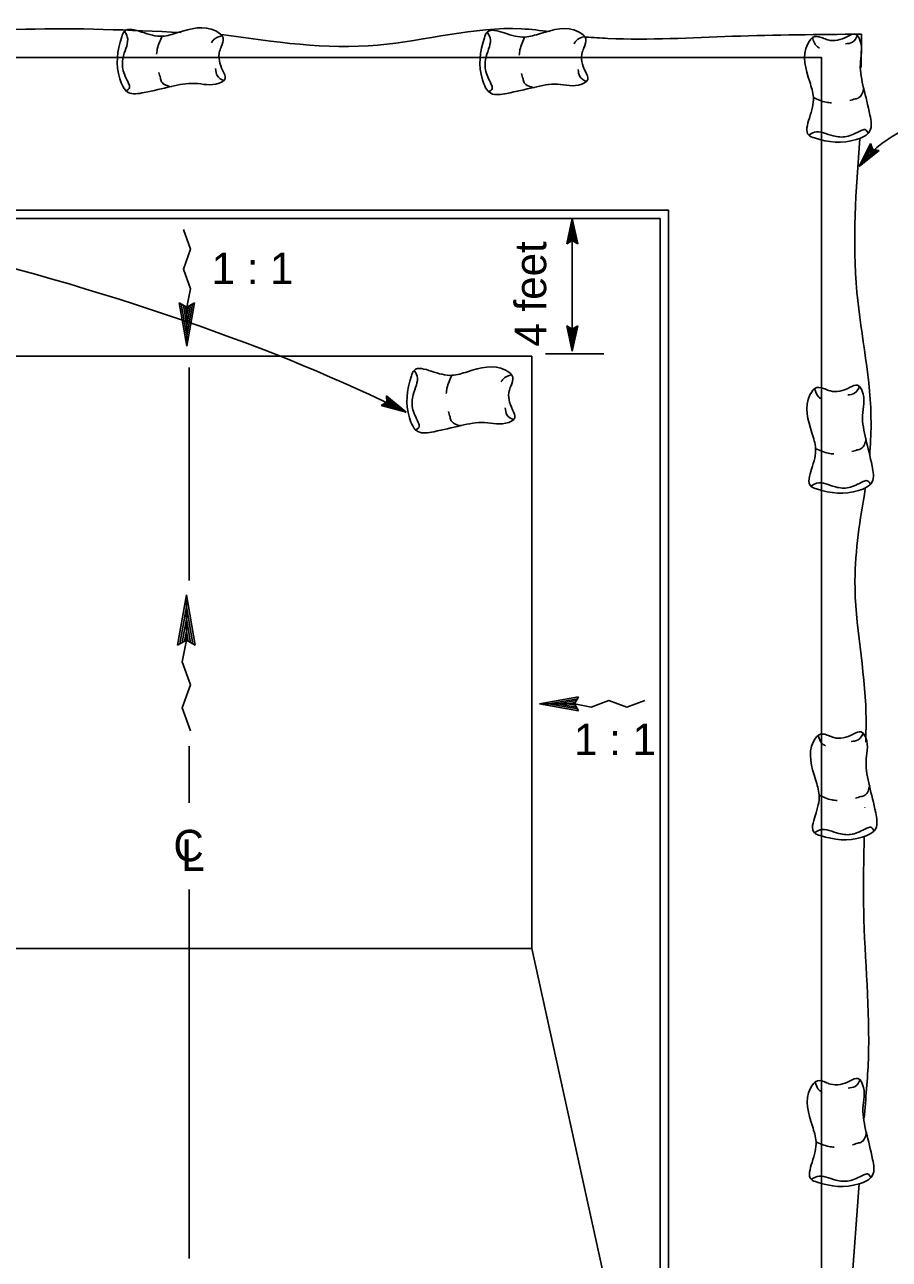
# Model space of a CAD drawing. Extents: x 6707406 to 6714471, y 1868570 to 1872341.
# Drawn here: x 6709027.7 to 6709225.4, y 1868819.1 to 1869101.6 of the extents above; entities that cross this region are included whole.
import ezdxf

# ---------------------------------------------------------------- set-up
doc = ezdxf.new("R2010")
doc.units = 0
for name, color, linetype in [('56 Stg 3 Anno', 7, 'Continuous'), ('57 Undefined', 7, 'Continuous'), ('60 Nongeo Data', 7, 'Continuous')]:
    doc.layers.add(name, color=color, linetype=linetype)

msp = doc.modelspace()

# ---------------------------------------------------------------- linework, layer by layer
at = {"layer": '56 Stg 3 Anno'}
for p, q in [((6709218.56, 1869069.08), (6709221.13, 1869074.39)), ((6709219.39, 1869070.13), (6709221.26, 1869074)), ((6709220.21, 1869071.16), (6709221.42, 1869073.66)), ((6709221.03, 1869072.2), (6709221.55, 1869073.27)), ((6709221.13, 1869074.39), (6709221.13, 1869074.39)), ((6709221.13, 1869074.39), (6709221.66, 1869073)), ((6709223.14, 1869072.8), (6709218.56, 1869069.08)), ((6709222.74, 1869072.85), (6709219.38, 1869070.12)), ((6709222.33, 1869072.89), (6709220.21, 1869071.16)), ((6709221.97, 1869072.96), (6709221.03, 1869072.2)), ((6709221.66, 1869073), (6709223.14, 1869072.8)), ((6709223.14, 1869072.8), (6709223.14, 1869072.8)), ((6709218.56, 1869069.08), (6709218.56, 1869069.08)), ((6709151.64, 1869051.43), (6709152.93, 1869057.19)), ((6709151.64, 1869051.43), (6709152.93, 1869057.19)), ((6709152.93, 1869026.86), (6709152.93, 1869057.19)), ((6709152.93, 1869057.19), (6709152.93, 1869057.19)), ((6709152.93, 1869057.19), (6709154.21, 1869051.43)), ((6709152.93, 1869057.19), (6709152.93, 1869057.19)), ((6709152.93, 1869057.19), (6709154.21, 1869051.43)), ((6709151.98, 1869051.64), (6709152.93, 1869055.87)), ((6709151.98, 1869051.64), (6709152.93, 1869055.87)), ((6709152.33, 1869051.87), (6709152.93, 1869054.54)), ((6709152.33, 1869051.87), (6709152.93, 1869054.54)), ((6709152.93, 1869055.86), (6709153.86, 1869051.66)), ((6709152.93, 1869055.86), (6709153.86, 1869051.66)), ((6709152.93, 1869054.54), (6709153.53, 1869051.83)), ((6709152.93, 1869054.54), (6709153.53, 1869051.83)), ((6709152.93, 1869052.2), (6709151.64, 1869051.43)), ((6709152.93, 1869052.2), (6709151.64, 1869051.43)), ((6709151.64, 1869051.43), (6709151.64, 1869051.43)), ((6709151.64, 1869051.43), (6709151.64, 1869051.43)), ((6709152.66, 1869052.04), (6709152.93, 1869053.22)), ((6709152.66, 1869052.04), (6709152.93, 1869053.22)), ((6709152.93, 1869053.22), (6709153.18, 1869052.05)), ((6709152.93, 1869053.22), (6709153.18, 1869052.05)), ((6709154.21, 1869051.43), (6709152.93, 1869052.2)), ((6709154.21, 1869051.43), (6709152.93, 1869052.2)), ((6709154.21, 1869051.43), (6709154.21, 1869051.43)), ((6709154.21, 1869051.43), (6709154.21, 1869051.43)), ((6709064.77, 1869028.01), (6709063.02, 1869037.91)), ((6709063.02, 1869037.91), (6709064.77, 1869036.89)), ((6709064.77, 1869030.38), (6709063.48, 1869037.64)), ((6709064.77, 1869032.73), (6709063.95, 1869037.36)), ((6709064.77, 1869035.13), (6709064.42, 1869037.09)), ((6709066.51, 1869037.91), (6709064.77, 1869028.01)), ((6709064.77, 1869036.89), (6709066.51, 1869037.91)), ((6709066.05, 1869037.64), (6709064.77, 1869030.38)), ((6709065.58, 1869037.36), (6709064.77, 1869032.73)), ((6709065.11, 1869037.09), (6709064.77, 1869035.13)), ((6709152.93, 1869026.86), (6709151.65, 1869032.62)), ((6709151.65, 1869032.62), (6709151.65, 1869032.62)), ((6709151.65, 1869032.62), (6709152.93, 1869031.86)), ((6709152.93, 1869028.2), (6709152, 1869032.4)), ((6709152.93, 1869029.52), (6709152.33, 1869032.23)), ((6709152.93, 1869030.84), (6709152.67, 1869032)), ((6709152.93, 1869031.86), (6709154.22, 1869032.62)), ((6709154.22, 1869032.62), (6709152.93, 1869026.86)), ((6709153.87, 1869032.42), (6709152.93, 1869028.19)), ((6709153.53, 1869032.19), (6709152.93, 1869029.52)), ((6709153.2, 1869032.02), (6709152.93, 1869030.84)), ((6709154.22, 1869032.62), (6709154.22, 1869032.62)), ((6709146.76, 1869026.26), (6709160.13, 1869026.26)), ((6709152.93, 1869026.86), (6709152.93, 1869026.86)), ((6709065.3, 1868974.39), (6709065.3, 1869023.08)), ((6709109.21, 1869014.39), (6709110.49, 1869015.17)), ((6709114.91, 1869012.86), (6709109.21, 1869014.39)), ((6709109.21, 1869014.39), (6709109.21, 1869014.39)), ((6709113.73, 1869013.47), (6709109.57, 1869014.59)), ((6709112.56, 1869014.09), (6709109.88, 1869014.81)), ((6709111.39, 1869014.7), (6709110.24, 1869015.01)), ((6709110.49, 1869015.17), (6709110.4, 1869016.66)), ((6709110.4, 1869016.66), (6709110.4, 1869016.66)), ((6709110.4, 1869016.66), (6709114.91, 1869012.86)), ((6709110.43, 1869016.26), (6709113.74, 1869013.47)), ((6709110.46, 1869015.48), (6709111.39, 1869014.7)), ((6709110.47, 1869015.85), (6709112.56, 1869014.09)), ((6709114.91, 1869012.86), (6709114.91, 1869012.86)), ((6709062.6, 1868959.55), (6709064.64, 1868971.09)), ((6709064.64, 1868971.09), (6709066.68, 1868959.55)), ((6709063.14, 1868959.86), (6709064.64, 1868968.33)), ((6709064.64, 1868968.33), (6709066.14, 1868959.86)), ((6709063.69, 1868960.18), (6709064.64, 1868965.59)), ((6709064.64, 1868965.59), (6709065.59, 1868960.18)), ((6709064.64, 1868960.73), (6709062.6, 1868959.55)), ((6709064.24, 1868960.5), (6709064.64, 1868962.78)), ((6709064.64, 1868962.78), (6709065.04, 1868960.5)), ((6709066.68, 1868959.55), (6709064.64, 1868960.73)), ((6709145.4, 1868946.17), (6709154.33, 1868947.75)), ((6709154.33, 1868944.6), (6709145.4, 1868946.17)), ((6709147.53, 1868946.17), (6709154.08, 1868947.33)), ((6709154.08, 1868945.01), (6709147.53, 1868946.17)), ((6709149.65, 1868946.17), (6709153.84, 1868946.91)), ((6709153.84, 1868945.44), (6709149.65, 1868946.17)), ((6709151.82, 1868946.17), (6709153.59, 1868946.49)), ((6709153.59, 1868945.86), (6709151.82, 1868946.17)), ((6709154.33, 1868947.75), (6709153.42, 1868946.17)), ((6709153.42, 1868946.17), (6709154.33, 1868944.6)), ((6709065.3, 1868923.55), (6709065.3, 1868936.5)), ((6709065.3, 1868819.27), (6709065.3, 1868903.71))]:
    msp.add_line(p, q, dxfattribs=at)
for points in [[(6709063.95, 1869054.7), (6709065.58, 1869050.17), (6709063.95, 1869045.64), (6709065.58, 1869041.11), (6709064.77, 1869036.89), (6709064.77, 1869028.01)], [(6709065.59, 1868939.96), (6709063.69, 1868945.24), (6709065.59, 1868950.53), (6709063.69, 1868955.81), (6709064.64, 1868960.73), (6709064.64, 1868971.09)], [(6709169.49, 1868946.91), (6709165.4, 1868945.44), (6709161.31, 1868946.91), (6709157.22, 1868945.44), (6709153.42, 1868946.17), (6709145.4, 1868946.17)]]:
    msp.add_lwpolyline(points, dxfattribs=at)
for centre, major_axis, ratio, start_param, end_param in [((6709230.16, 1869064.46), (-14.41, -12.25), 0.619917, 3.775635, 5.024737), ((6708995.51, 1869014.62), (158.62, -38.37), 0.230593, 0.776019, 2.395591)]:
    msp.add_ellipse(centre, major_axis=major_axis, ratio=ratio, start_param=start_param, end_param=end_param, dxfattribs=at)
at = {"layer": '60 Nongeo Data'}
for p, q in [((6709219.12, 1869099.36), (6709218.98, 1869091.78)), ((6709219.85, 1868922.53), (6709219.85, 1868922.43)), ((6708987.05, 1868890.2), (6709143.66, 1868890.2)), ((6709218.56, 1868836.41), (6709214.73, 1868784.37))]:
    msp.add_line(p, q, dxfattribs=at)
for points in [[(6708920.45, 1868713.46), (6708920.45, 1869094.08), (6709209.91, 1869094.08), (6709209.91, 1868713.46)], [(6708955.42, 1868754.11), (6708955.42, 1869059.11), (6709174.94, 1869059.11), (6709174.94, 1868765.65)], [(6708957.34, 1868756.03), (6708957.34, 1869057.19), (6709173.02, 1869057.19), (6709173.02, 1868756.03)], [(6708987.05, 1869025.72), (6709143.66, 1869025.72)], [(6709143.66, 1869025.72), (6709143.66, 1868890.2)], [(6709143.66, 1868890.2), (6709172.98, 1868757)]]:
    msp.add_lwpolyline(points, dxfattribs=at)
for points in [[(6709072.63, 1869096.47), (6709073.03, 1869098.51), (6709071.38, 1869100.11), (6709062.69, 1869099.73), (6709059.14, 1869098.92), (6709054.39, 1869099.87), (6709050.47, 1869100.05), (6709049.85, 1869098.77), (6709049.4, 1869089.16), (6709051.34, 1869086.05), (6709054.96, 1869086.02), (6709061.16, 1869087.41), (6709066.6, 1869088.12), (6709072.11, 1869088.15), (6709073.48, 1869089.2), (6709072.97, 1869091.02), (6709072.25, 1869095.49), (6709072.71, 1869096.7)], [(6708993.28, 1869097.73), (6709027.81, 1869100.5), (6709063.48, 1869099.77)], [(6709050.47, 1869100.13), (6709051.13, 1869098.76), (6709050.27, 1869094.45), (6709050.09, 1869091.43), (6709051.43, 1869088.09), (6709051.65, 1869087.18), (6709050.66, 1869086.35)], [(6709059.14, 1869099), (6709057.98, 1869095.98), (6709057.82, 1869094.77)], [(6709072.81, 1869099.04), (6709070.84, 1869098.07), (6709070.38, 1869097.4)], [(6709072.66, 1869099.34), (6709108.46, 1869096.89), (6709141.34, 1869100.6), (6709147.79, 1869099.97)], [(6709155.6, 1869096.27), (6709155.99, 1869098.31), (6709154.34, 1869099.91), (6709145.66, 1869099.53), (6709142.1, 1869098.72), (6709137.35, 1869099.67), (6709133.43, 1869099.85), (6709132.81, 1869098.57), (6709132.36, 1869088.97), (6709134.3, 1869085.85), (6709137.92, 1869085.82), (6709144.13, 1869087.21), (6709149.57, 1869087.92), (6709155.08, 1869087.95), (6709156.45, 1869089), (6709155.93, 1869090.82), (6709155.21, 1869095.29), (6709155.68, 1869096.5)], [(6709133.43, 1869099.93), (6709134.1, 1869098.56), (6709133.23, 1869094.26), (6709133.06, 1869091.23), (6709134.39, 1869087.89), (6709134.61, 1869086.98), (6709133.62, 1869086.16)], [(6709142.1, 1869098.8), (6709140.95, 1869095.78), (6709140.79, 1869094.57)], [(6709155.77, 1869098.84), (6709153.8, 1869097.87), (6709153.34, 1869097.2)], [(6709155.99, 1869098.71), (6709161.07, 1869098.41), (6709189.58, 1869098.9), (6709219.07, 1869099.38)], [(6709210.42, 1869098.45), (6709208.38, 1869098.83), (6709206.79, 1869097.17), (6709207.24, 1869088.49), (6709208.08, 1869084.94), (6709207.17, 1869080.18), (6709207.02, 1869076.26), (6709208.3, 1869075.65), (6709217.91, 1869075.28), (6709221.01, 1869077.24), (6709221.01, 1869080.86), (6709219.57, 1869087.05), (6709218.82, 1869092.49), (6709218.74, 1869098), (6709217.68, 1869099.36), (6709215.87, 1869098.83), (6709211.4, 1869098.08), (6709210.19, 1869098.53)], [(6709218.21, 1869099.21), (6709217, 1869097.55), (6709215.41, 1869097.17)], [(6709207.85, 1869098.6), (6709208.83, 1869096.64), (6709209.51, 1869096.19)], [(6709061.24, 1869087.33), (6709058.98, 1869088.48), (6709058.69, 1869089.39), (6709058.32, 1869090.61)], [(6709073.33, 1869088.67), (6709071.68, 1869089.89), (6709071.31, 1869091.49)], [(6709144.2, 1869087.13), (6709141.94, 1869088.28), (6709141.65, 1869089.19), (6709141.28, 1869090.41)], [(6709156.29, 1869088.47), (6709154.64, 1869089.7), (6709154.27, 1869091.29)], [(6709208, 1869084.94), (6709211.03, 1869083.81), (6709212.24, 1869083.66)], [(6709219.65, 1869087.13), (6709218.51, 1869084.86), (6709217.61, 1869084.56), (6709216.4, 1869084.19)], [(6709206.94, 1869076.26), (6709208.3, 1869076.94), (6709212.61, 1869076.11), (6709215.64, 1869075.96), (6709218.97, 1869077.31), (6709219.88, 1869077.54), (6709220.71, 1869076.56)], [(6709218.68, 1869075.48), (6709218.04, 1869040.32), (6709221.27, 1869010.15), (6709220.96, 1869002.95)], [(6709138.9, 1869018.88), (6709139.3, 1869020.92), (6709137.65, 1869022.52), (6709128.96, 1869022.14), (6709125.41, 1869021.33), (6709120.66, 1869022.28), (6709116.73, 1869022.46), (6709116.12, 1869021.18), (6709115.67, 1869011.58), (6709117.6, 1869008.46), (6709121.23, 1869008.43), (6709127.43, 1869009.82), (6709132.87, 1869010.53), (6709138.38, 1869010.56), (6709139.75, 1869011.61), (6709139.24, 1869013.43), (6709138.52, 1869017.9), (6709138.98, 1869019.11)], [(6709116.73, 1869022.54), (6709117.4, 1869021.17), (6709116.54, 1869016.87), (6709116.36, 1869013.84), (6709117.7, 1869010.5), (6709117.91, 1869009.59), (6709116.93, 1869008.77)], [(6709125.41, 1869021.41), (6709124.25, 1869018.39), (6709124.09, 1869017.18)], [(6709139.07, 1869021.45), (6709137.1, 1869020.48), (6709136.64, 1869019.81)], [(6709210.93, 1869018.14), (6709208.88, 1869018.52), (6709207.3, 1869016.85), (6709207.75, 1869008.17), (6709208.58, 1869004.62), (6709207.67, 1868999.87), (6709207.52, 1868995.94), (6709208.81, 1868995.34), (6709218.42, 1868994.96), (6709221.52, 1868996.92), (6709221.52, 1869000.55), (6709220.08, 1869006.74), (6709219.32, 1869012.17), (6709219.25, 1869017.69), (6709218.19, 1869019.04), (6709216.37, 1869018.52), (6709211.91, 1869017.76), (6709210.7, 1869018.21)], [(6709208.35, 1869018.29), (6709209.34, 1869016.33), (6709210.02, 1869015.87)], [(6709218.72, 1869018.89), (6709217.51, 1869017.23), (6709215.92, 1869016.85)], [(6709139.6, 1869011.08), (6709137.94, 1869012.31), (6709137.58, 1869013.9)], [(6709127.5, 1869009.74), (6709125.25, 1869010.89), (6709124.95, 1869011.8), (6709124.59, 1869013.02)], [(6709220.16, 1869006.81), (6709219.02, 1869004.55), (6709218.11, 1869004.25), (6709216.9, 1869003.87)], [(6709208.51, 1869004.62), (6709211.53, 1869003.49), (6709212.74, 1869003.34)], [(6709207.45, 1868995.94), (6709208.81, 1868996.62), (6709213.12, 1868995.79), (6709216.15, 1868995.64), (6709219.47, 1868997), (6709220.38, 1868997.22), (6709221.21, 1868996.24)], [(6709219.96, 1868995.37), (6709217.58, 1868974.32), (6709220.11, 1868943.98), (6709220.06, 1868937.4)], [(6709211.74, 1868938.83), (6709209.69, 1868939.21), (6709208.1, 1868937.55), (6709208.56, 1868928.87), (6709209.39, 1868925.32), (6709208.48, 1868920.56), (6709208.33, 1868916.63), (6709209.62, 1868916.03), (6709219.23, 1868915.65), (6709222.33, 1868917.62), (6709222.33, 1868921.24), (6709220.89, 1868927.43), (6709220.13, 1868932.87), (6709220.06, 1868938.38), (6709219, 1868939.74), (6709217.18, 1868939.21), (6709212.72, 1868938.45), (6709211.51, 1868938.91)], [(6709209.16, 1868938.98), (6709210.15, 1868937.02), (6709210.83, 1868936.57)], [(6709219.53, 1868939.59), (6709218.32, 1868937.92), (6709216.73, 1868937.55)], [(6709220.97, 1868927.51), (6709219.83, 1868925.24), (6709218.92, 1868924.94), (6709217.71, 1868924.56)], [(6709209.32, 1868925.32), (6709212.34, 1868924.18), (6709213.55, 1868924.03)], [(6709208.26, 1868916.63), (6709209.62, 1868917.31), (6709213.93, 1868916.48), (6709216.96, 1868916.33), (6709220.28, 1868917.69), (6709221.19, 1868917.92), (6709222.02, 1868916.94)], [(6709219.71, 1868915.75), (6709219.58, 1868898.94), (6709220.65, 1868864.76), (6709219.66, 1868851.34)], [(6709211.03, 1868859.52), (6709208.99, 1868859.9), (6709207.4, 1868858.24), (6709207.85, 1868849.56), (6709208.68, 1868846.01), (6709207.78, 1868841.25), (6709207.62, 1868837.33), (6709208.91, 1868836.72), (6709218.52, 1868836.34), (6709221.62, 1868838.31), (6709221.62, 1868841.93), (6709220.18, 1868848.12), (6709219.42, 1868853.56), (6709219.35, 1868859.07), (6709218.29, 1868860.43), (6709216.47, 1868859.9), (6709212.01, 1868859.15), (6709210.8, 1868859.6)], [(6709208.46, 1868859.67), (6709209.44, 1868857.71), (6709210.12, 1868857.26)], [(6709218.82, 1868860.28), (6709217.61, 1868858.62), (6709216.02, 1868858.24)], [(6709220.26, 1868848.2), (6709219.12, 1868845.93), (6709218.21, 1868845.63), (6709217, 1868845.25)], [(6709208.61, 1868846.01), (6709211.63, 1868844.88), (6709212.84, 1868844.73)], [(6709207.55, 1868837.33), (6709208.91, 1868838.01), (6709213.22, 1868837.18), (6709216.25, 1868837.02), (6709219.58, 1868838.38), (6709220.48, 1868838.61), (6709221.32, 1868837.63)]]:
    msp.add_spline(points, degree=3, dxfattribs=at)

# ---------------------------------------------------------------- texts
at = {"layer": '57 Undefined'}
msp.add_text('4 feet', height=7.2, rotation=90, dxfattribs=at).set_placement((6709146.96, 1869027.91))
for s, p in [('1 : 1', (6709070.4, 1869042.19)), ('1 : 1', (6709153.33, 1868934.43)), ('C', (6709061.67, 1868910.14)), ('L', (6709063.47, 1868907.95))]:
    msp.add_text(s, height=7.2, dxfattribs=at).set_placement(p)

doc.saveas('drawing.dxf')
